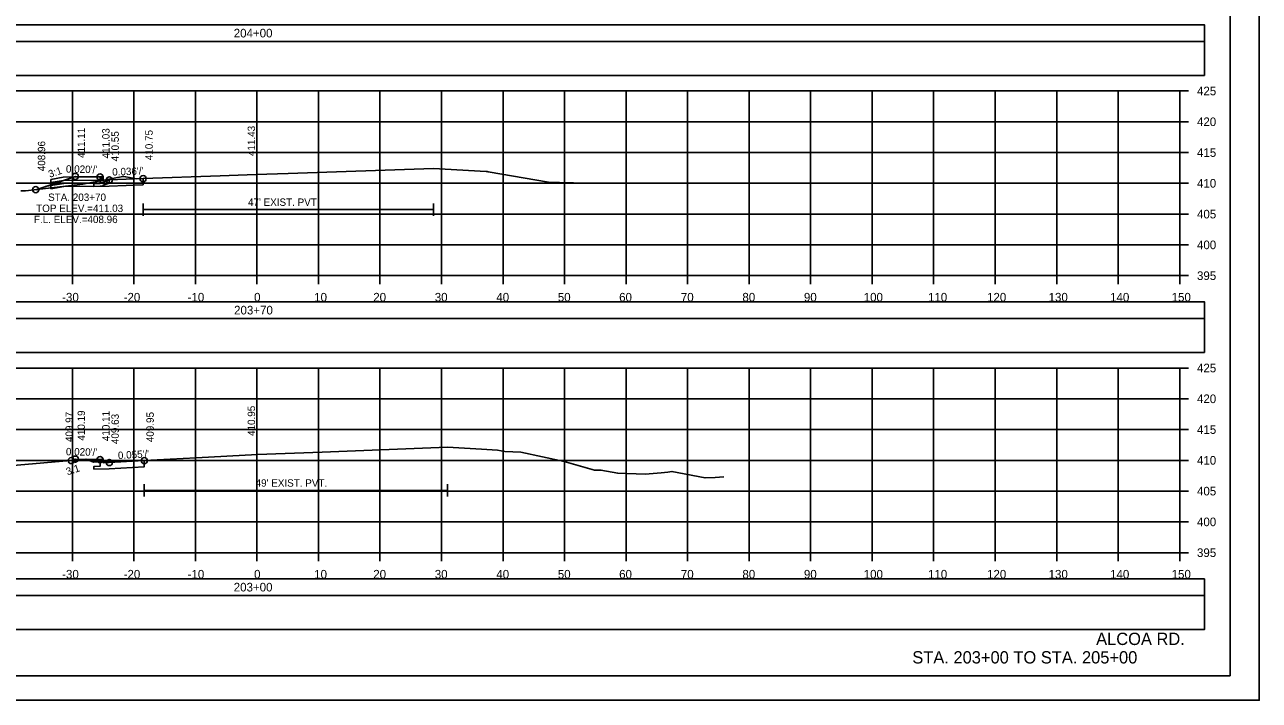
# Model space of a CAD drawing. Extents: x 1371057 to 1372761, y 380005 to 390517.
# Drawn here: x 1372113 to 1372313.6, y 389450.5 to 389560.2 of the extents above; entities that cross this region are included whole.
import ezdxf

# ---------------------------------------------------------------- set-up
doc = ezdxf.new("R2010")
doc.units = 0
for name, color, linetype in [('R_Alt Surface', 7, 'Continuous'), ('R_Axis', 7, 'Continuous'), ('R_Axis Annot', 7, 'Continuous'), ('R_Border', 7, 'Continuous'), ('R_Dimension', 7, 'Continuous'), ('R_Draft', 7, 'Continuous'), ('R_Exist Surface', 7, 'Continuous'), ('R_Fin Surface', 7, 'Continuous'), ('R_Grid', 7, 'Continuous'), ('R_No Plot', 7, 'Continuous'), ('R_Water', 7, 'Continuous'), ('R_Water Annot', 7, 'Continuous'), ('R_Xsect Elev', 7, 'Continuous'), ('R_Xsect Slope', 7, 'Continuous')]:
    doc.layers.add(name, color=color, linetype=linetype)

msp = doc.modelspace()

# ---------------------------------------------------------------- linework, layer by layer
at = {"layer": 'R_Alt Surface'}
for p, q in [((1372132.22, 389529.21), (1372132.22, 389531.21)), ((1372132.22, 389530.21), (1372179.39, 389530.21)), ((1372179.39, 389529.21), (1372179.39, 389531.21)), ((1372132.4, 389483.59), (1372132.4, 389485.59)), ((1372181.7, 389483.59), (1372181.7, 389485.59)), ((1372132.4, 389484.59), (1372181.7, 389484.59))]:
    msp.add_line(p, q, dxfattribs=at)
for points in [[(1372132.22, 389535.23), (1372132.22, 389534.23), (1372126.71, 389534.02), (1372124.21, 389533.97), (1372124.21, 389534.4), (1372125.21, 389534.42), (1372125.21, 389535.51)], [(1372132.4, 389489.42), (1372132.4, 389488.42), (1372126.71, 389488.11), (1372124.21, 389488.06), (1372124.21, 389488.49), (1372125.21, 389488.51), (1372125.21, 389489.59)]]:
    msp.add_lwpolyline(points, dxfattribs=at)
at = {"layer": 'R_Axis'}
for p, q in [((1372300.71, 389519.47), (1372300.71, 389549.47)), ((1372302.11, 389549.47), (1372300.71, 389549.47)), ((1372302.11, 389544.47), (1372300.71, 389544.47)), ((1372302.11, 389539.47), (1372300.71, 389539.47)), ((1372302.11, 389534.47), (1372300.71, 389534.47)), ((1372302.11, 389529.47), (1372300.71, 389529.47)), ((1372302.11, 389524.47), (1372300.71, 389524.47)), ((1372000.71, 389519.47), (1372300.71, 389519.47)), ((1372120.71, 389518.07), (1372120.71, 389519.47)), ((1372130.71, 389518.07), (1372130.71, 389519.47)), ((1372140.71, 389518.07), (1372140.71, 389519.47)), ((1372150.71, 389518.07), (1372150.71, 389519.47)), ((1372160.71, 389518.07), (1372160.71, 389519.47)), ((1372170.71, 389518.07), (1372170.71, 389519.47)), ((1372180.71, 389518.07), (1372180.71, 389519.47)), ((1372190.71, 389518.07), (1372190.71, 389519.47)), ((1372200.71, 389518.07), (1372200.71, 389519.47)), ((1372210.71, 389518.07), (1372210.71, 389519.47)), ((1372220.71, 389518.07), (1372220.71, 389519.47)), ((1372230.71, 389518.07), (1372230.71, 389519.47)), ((1372240.71, 389518.07), (1372240.71, 389519.47)), ((1372250.71, 389518.07), (1372250.71, 389519.47)), ((1372260.71, 389518.07), (1372260.71, 389519.47)), ((1372270.71, 389518.07), (1372270.71, 389519.47)), ((1372280.71, 389518.07), (1372280.71, 389519.47)), ((1372290.71, 389518.07), (1372290.71, 389519.47)), ((1372300.71, 389518.07), (1372300.71, 389519.47)), ((1372302.11, 389519.47), (1372300.71, 389519.47)), ((1372300.71, 389474.47), (1372300.71, 389504.47)), ((1372302.11, 389504.47), (1372300.71, 389504.47)), ((1372302.11, 389499.47), (1372300.71, 389499.47)), ((1372302.11, 389494.47), (1372300.71, 389494.47)), ((1372302.11, 389489.47), (1372300.71, 389489.47)), ((1372302.11, 389484.47), (1372300.71, 389484.47)), ((1372302.11, 389479.47), (1372300.71, 389479.47)), ((1372000.71, 389474.47), (1372300.71, 389474.47)), ((1372120.71, 389473.07), (1372120.71, 389474.47)), ((1372130.71, 389473.07), (1372130.71, 389474.47)), ((1372140.71, 389473.07), (1372140.71, 389474.47)), ((1372150.71, 389473.07), (1372150.71, 389474.47)), ((1372160.71, 389473.07), (1372160.71, 389474.47)), ((1372170.71, 389473.07), (1372170.71, 389474.47)), ((1372180.71, 389473.07), (1372180.71, 389474.47)), ((1372190.71, 389473.07), (1372190.71, 389474.47)), ((1372200.71, 389473.07), (1372200.71, 389474.47)), ((1372210.71, 389473.07), (1372210.71, 389474.47)), ((1372220.71, 389473.07), (1372220.71, 389474.47)), ((1372230.71, 389473.07), (1372230.71, 389474.47)), ((1372240.71, 389473.07), (1372240.71, 389474.47)), ((1372250.71, 389473.07), (1372250.71, 389474.47)), ((1372260.71, 389473.07), (1372260.71, 389474.47)), ((1372270.71, 389473.07), (1372270.71, 389474.47)), ((1372280.71, 389473.07), (1372280.71, 389474.47)), ((1372290.71, 389473.07), (1372290.71, 389474.47)), ((1372300.71, 389473.07), (1372300.71, 389474.47)), ((1372302.11, 389474.47), (1372300.71, 389474.47))]:
    msp.add_line(p, q, dxfattribs=at)
at = {"layer": 'R_Border'}
for q in [(1372308.89, 389659.93), (1371992.71, 389454.47)]:
    msp.add_line((1372308.89, 389454.47), q, dxfattribs=at)
at = {"layer": 'R_Dimension'}
for points in [[(1371996.71, 389557.52), (1372304.71, 389557.52), (1372304.71, 389560.22), (1371996.71, 389560.22)], [(1371996.71, 389551.99), (1372304.71, 389551.99), (1372304.71, 389557.52), (1371996.71, 389557.52)], [(1371996.71, 389512.52), (1372304.71, 389512.52), (1372304.71, 389515.22), (1371996.71, 389515.22)], [(1371996.71, 389506.99), (1372304.71, 389506.99), (1372304.71, 389512.52), (1371996.71, 389512.52)], [(1371996.71, 389467.52), (1372304.71, 389467.52), (1372304.71, 389470.22), (1371996.71, 389470.22)], [(1371996.71, 389461.99), (1372304.71, 389461.99), (1372304.71, 389467.52), (1371996.71, 389467.52)]]:
    msp.add_lwpolyline(points, close=True, dxfattribs=at)
at = {"layer": 'R_Exist Surface'}
for points in [[(1372112.35, 389533.23), (1372113.09, 389533.24), (1372122.41, 389534.33), (1372128.9, 389535.6), (1372128.95, 389535.6), (1372128.97, 389535.53), (1372128.99, 389535.6), (1372129.04, 389535.57), (1372129.38, 389535.51), (1372131.19, 389535.21), (1372132.22, 389535.23), (1372144.73, 389535.67), (1372150.57, 389535.89), (1372155.78, 389536.07), (1372179.39, 389536.88), (1372187.96, 389536.39), (1372188.13, 389536.38), (1372188.28, 389536.35), (1372198.11, 389534.66), (1372199.89, 389534.61), (1372204.42, 389534.48)], [(1372101.13, 389487.74), (1372122.91, 389489.65), (1372123.34, 389489.48), (1372124.14, 389489.16), (1372126.66, 389489.26), (1372132.4, 389489.42), (1372140.81, 389489.86), (1372150.82, 389490.43), (1372161.29, 389490.82), (1372181.7, 389491.6), (1372187.2, 389491.26), (1372189.81, 389491.12), (1372190.99, 389490.91), (1372193.63, 389490.78), (1372200.67, 389489.26), (1372205.59, 389487.9), (1372206.63, 389487.88), (1372209.37, 389487.36), (1372213.8, 389487.2), (1372216.4, 389487.43), (1372217.5, 389487.54), (1372218.16, 389487.67), (1372223.56, 389486.62), (1372225.19, 389486.7), (1372226.6, 389486.79)]]:
    msp.add_lwpolyline(points, dxfattribs=at)
at = {"layer": 'R_Fin Surface'}
for points in [[(1372114.75, 389533.43), (1372121.21, 389535.59), (1372125.21, 389535.51), (1372125.71, 389535.51), (1372125.71, 389535.01), (1372126.71, 389535.03), (1372132.22, 389535.23)], [(1372120.52, 389489.44), (1372121.21, 389489.67), (1372125.21, 389489.59), (1372125.71, 389489.59), (1372125.71, 389489.09), (1372126.71, 389489.11), (1372132.4, 389489.42)]]:
    msp.add_lwpolyline(points, dxfattribs=at)
at = {"layer": 'R_Grid'}
for p, q in [((1372000.71, 389549.47), (1372300.71, 389549.47)), ((1372120.71, 389519.47), (1372120.71, 389549.47)), ((1372130.71, 389519.47), (1372130.71, 389549.47)), ((1372140.71, 389519.47), (1372140.71, 389549.47)), ((1372150.71, 389519.47), (1372150.71, 389549.47)), ((1372160.71, 389519.47), (1372160.71, 389549.47)), ((1372170.71, 389519.47), (1372170.71, 389549.47)), ((1372180.71, 389519.47), (1372180.71, 389549.47)), ((1372190.71, 389519.47), (1372190.71, 389549.47)), ((1372200.71, 389519.47), (1372200.71, 389549.47)), ((1372210.71, 389519.47), (1372210.71, 389549.47)), ((1372220.71, 389519.47), (1372220.71, 389549.47)), ((1372230.71, 389519.47), (1372230.71, 389549.47)), ((1372240.71, 389519.47), (1372240.71, 389549.47)), ((1372250.71, 389519.47), (1372250.71, 389549.47)), ((1372260.71, 389519.47), (1372260.71, 389549.47)), ((1372270.71, 389519.47), (1372270.71, 389549.47)), ((1372280.71, 389519.47), (1372280.71, 389549.47)), ((1372290.71, 389519.47), (1372290.71, 389549.47)), ((1372300.71, 389519.47), (1372300.71, 389549.47)), ((1372000.71, 389544.47), (1372300.71, 389544.47)), ((1372000.71, 389539.47), (1372300.71, 389539.47)), ((1372000.71, 389534.47), (1372300.71, 389534.47)), ((1372000.71, 389529.47), (1372300.71, 389529.47)), ((1372000.71, 389524.47), (1372300.71, 389524.47)), ((1372000.71, 389519.47), (1372300.71, 389519.47)), ((1372000.71, 389504.47), (1372300.71, 389504.47)), ((1372120.71, 389474.47), (1372120.71, 389504.47)), ((1372130.71, 389474.47), (1372130.71, 389504.47)), ((1372140.71, 389474.47), (1372140.71, 389504.47)), ((1372150.71, 389474.47), (1372150.71, 389504.47)), ((1372160.71, 389474.47), (1372160.71, 389504.47)), ((1372170.71, 389474.47), (1372170.71, 389504.47)), ((1372180.71, 389474.47), (1372180.71, 389504.47)), ((1372190.71, 389474.47), (1372190.71, 389504.47)), ((1372200.71, 389474.47), (1372200.71, 389504.47)), ((1372210.71, 389474.47), (1372210.71, 389504.47)), ((1372220.71, 389474.47), (1372220.71, 389504.47)), ((1372230.71, 389474.47), (1372230.71, 389504.47)), ((1372240.71, 389474.47), (1372240.71, 389504.47)), ((1372250.71, 389474.47), (1372250.71, 389504.47)), ((1372260.71, 389474.47), (1372260.71, 389504.47)), ((1372270.71, 389474.47), (1372270.71, 389504.47)), ((1372280.71, 389474.47), (1372280.71, 389504.47)), ((1372290.71, 389474.47), (1372290.71, 389504.47)), ((1372300.71, 389474.47), (1372300.71, 389504.47)), ((1372000.71, 389499.47), (1372300.71, 389499.47)), ((1372000.71, 389494.47), (1372300.71, 389494.47)), ((1372000.71, 389489.47), (1372300.71, 389489.47)), ((1372000.71, 389484.47), (1372300.71, 389484.47)), ((1372000.71, 389479.47), (1372300.71, 389479.47)), ((1372000.71, 389474.47), (1372300.71, 389474.47))]:
    msp.add_line(p, q, dxfattribs=at)
at = {"layer": 'R_No Plot'}
msp.add_line((1371980.31, 389450.49), (1372313.64, 389450.49), dxfattribs=at)
for points in [[(1371980.3, 389663.83), (1372313.64, 389663.83), (1372313.64, 389450.49), (1371980.3, 389450.49)], [(1372226.63, 389659.93), (1372246.25, 389659.93), (1372246.25, 389650.05), (1372262.36, 389650.05), (1372285.56, 389650.05), (1372285.68, 389621.9), (1372308.89, 389621.9), (1372308.89, 389454.47), (1371992.71, 389454.47), (1371992.71, 389659.93)]]:
    msp.add_lwpolyline(points, close=True, dxfattribs=at)
for centre in [(1372121.21, 389535.59), (1372125.21, 389535.51), (1372132.22, 389535.23), (1372114.75, 389533.43), (1372126.71, 389535.03), (1372120.52, 389489.44), (1372121.21, 389489.67), (1372125.21, 389489.59), (1372126.71, 389489.11), (1372132.4, 389489.42)]:
    msp.add_circle(centre, 0.5, dxfattribs=at)
at = {"layer": 'R_Water'}
for p, q in [((1372117.21, 389534.1), (1372116.29, 389533.95)), ((1372119.2, 389535.45), (1372117.21, 389535.11)), ((1372117.21, 389535.11), (1372117.21, 389533.59)), ((1372119.25, 389534.95), (1372117.21, 389534.61)), ((1372119.34, 389533.95), (1372117.21, 389533.59)), ((1372119.32, 389534.45), (1372117.22, 389534.1)), ((1372125.21, 389535.5), (1372119.2, 389535.45)), ((1372125.21, 389535), (1372119.25, 389534.95)), ((1372125.21, 389534.51), (1372119.32, 389534.45)), ((1372125.21, 389534.01), (1372119.34, 389533.95))]:
    msp.add_line(p, q, dxfattribs=at)
for points in [[(1372125.21, 389535.5), (1372125.46, 389535.5), (1372125.54, 389535.34), (1372125.21, 389535)], [(1372125.21, 389534.51), (1372126.71, 389535.03), (1372126.71, 389534.5), (1372125.71, 389534.15), (1372125.71, 389534.01), (1372125.21, 389534.01)]]:
    msp.add_lwpolyline(points, dxfattribs=at)
at = {"layer": 'R_Xsect Elev'}
for p, q in [((1372150.71, 389535.9), (1372150.71, 389545.9)), ((1372150.71, 389490.43), (1372150.71, 389500.43))]:
    msp.add_line(p, q, dxfattribs=at)

# ---------------------------------------------------------------- texts
at = {"layer": 'R_Axis Annot'}
for s, p in [('204+00', (1372146.94, 389558.17)), ('425', (1372303.51, 389548.77)), ('420', (1372303.51, 389543.77)), ('415', (1372303.51, 389538.77)), ('410', (1372303.51, 389533.77)), ('405', (1372303.51, 389528.77)), ('400', (1372303.51, 389523.77)), ('395', (1372303.51, 389518.77)), ('-30', (1372119.05, 389515.27)), ('-20', (1372129.05, 389515.27)), ('-10', (1372139.45, 389515.27)), ('0', (1372150.25, 389515.27)), ('10', (1372160.02, 389515.27)), ('20', (1372169.62, 389515.27)), ('30', (1372179.62, 389515.27)), ('40', (1372189.62, 389515.27)), ('50', (1372199.62, 389515.27)), ('60', (1372209.59, 389515.27)), ('70', (1372219.62, 389515.27)), ('80', (1372229.62, 389515.27)), ('90', (1372239.62, 389515.27)), ('100', (1372249.34, 389515.27)), ('110', (1372259.79, 389515.27)), ('120', (1372269.39, 389515.27)), ('130', (1372279.39, 389515.27)), ('140', (1372289.39, 389515.27)), ('150', (1372299.39, 389515.27)), ('203+70', (1372147, 389513.17)), ('425', (1372303.51, 389503.77)), ('420', (1372303.51, 389498.77)), ('415', (1372303.51, 389493.77)), ('410', (1372303.51, 389488.77)), ('405', (1372303.51, 389483.77)), ('400', (1372303.51, 389478.77)), ('395', (1372303.51, 389473.77)), ('-30', (1372119.05, 389470.27)), ('-20', (1372129.05, 389470.27)), ('-10', (1372139.45, 389470.27)), ('0', (1372150.25, 389470.27)), ('10', (1372160.02, 389470.27)), ('20', (1372169.62, 389470.27)), ('30', (1372179.62, 389470.27)), ('40', (1372189.62, 389470.27)), ('50', (1372199.62, 389470.27)), ('60', (1372209.59, 389470.27)), ('70', (1372219.62, 389470.27)), ('80', (1372229.62, 389470.27)), ('90', (1372239.62, 389470.27)), ('100', (1372249.34, 389470.27)), ('110', (1372259.79, 389470.27)), ('120', (1372269.39, 389470.27)), ('130', (1372279.39, 389470.27)), ('140', (1372289.39, 389470.27)), ('150', (1372299.39, 389470.27)), ('203+00', (1372146.94, 389468.17))]:
    msp.add_text(s, height=1.4, dxfattribs=at).set_placement(p)
at = {"layer": 'R_Draft'}
for s, p in [('ALCOA RD.', (1372287.12, 389459.47)), ('STA. 203+00 TO STA. 205+00', (1372257.24, 389456.47))]:
    msp.add_text(s, height=2, dxfattribs=at).set_placement(p)
at = {"layer": 'R_Water'}
for s, p in [("47' EXIST. PVT.", (1372149.26, 389530.81)), ("49' EXIST. PVT.", (1372150.5, 389485.19))]:
    msp.add_text(s, height=1.2, dxfattribs=at).set_placement(p)
at = {"layer": 'R_Water Annot'}
for s, p in [('STA. 203+70', (1372116.77, 389531.61)), ('TOP ELEV.=411.03', (1372114.83, 389529.81)), ('F.L. ELEV.=408.96', (1372114.47, 389528.01))]:
    msp.add_text(s, height=1.2, dxfattribs=at).set_placement(p)
at = {"layer": 'R_Xsect Elev'}
for s, p in [('411.43', (1372150.41, 389538.9)), ('411.11', (1372122.76, 389538.59)), ('411.03', (1372126.76, 389538.51)), ('410.55', (1372128.26, 389538.03)), ('410.75', (1372133.77, 389538.23)), ('408.96', (1372116.3, 389536.43)), ('410.19', (1372122.76, 389492.67)), ('410.95', (1372150.41, 389493.43)), ('409.97', (1372120.8, 389492.44)), ('410.11', (1372126.76, 389492.59)), ('409.63', (1372128.26, 389492.11)), ('409.95', (1372133.95, 389492.42))]:
    msp.add_text(s, height=1.2, rotation=90, dxfattribs=at).set_placement(p)
at = {"layer": 'R_Xsect Slope'}
for s, rotation, p in [('3:1', 18.4349, (1372117.03, 389535.36)), ("0.020'/'", 358.8542, (1372119.66, 389536.22)), ("0.036'/'", 2.0875, (1372127.21, 389535.72)), ("0.020'/'", 358.8542, (1372119.66, 389490.3)), ("0.055'/'", 3.1434, (1372128.15, 389489.67)), ('3:1', 18.4349, (1372119.92, 389487.02))]:
    msp.add_text(s, height=1.2, rotation=rotation, dxfattribs=at).set_placement(p)

doc.saveas('drawing.dxf')
